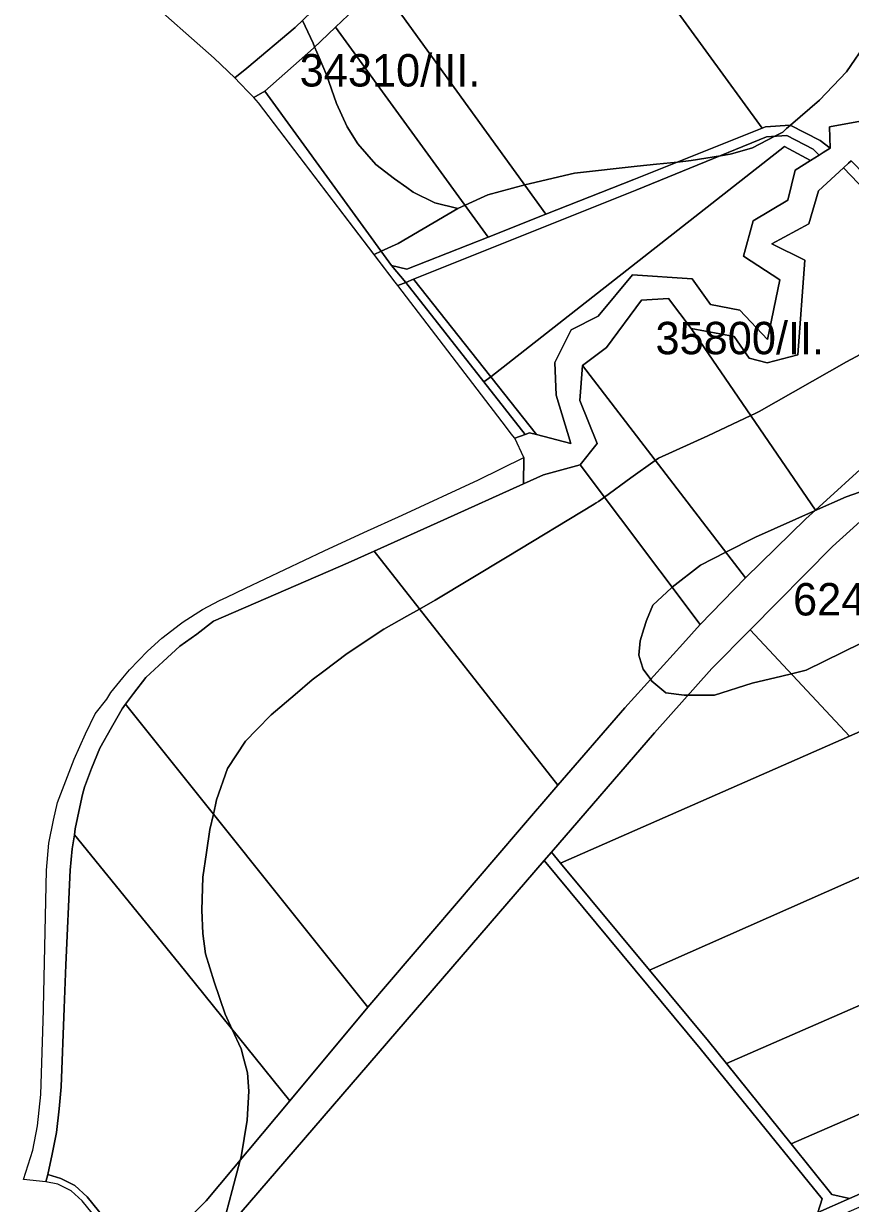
# Model space of a CAD drawing. Extents: x -522079 to -518792, y -1142400 to -1139961.
# Drawn here: x -521980 to -521597, y -1141010 to -1140463 of the extents above; entities that cross this region are included whole.
import ezdxf

# ---------------------------------------------------------------- set-up
doc = ezdxf.new("R2010")
doc.units = 0
for name, color, linetype in [('Hranice parcel', 7, 'Continuous'), ('Parcelní čísla', 7, 'Continuous'), ('Vnitřní kresba', 7, 'Continuous'), ('Značky bodu BP', 7, 'Continuous')]:
    doc.layers.add(name, color=color, linetype=linetype)

msp = doc.modelspace()

# ---------------------------------------------------------------- linework, layer by layer
at = {"layer": 'Hranice parcel'}
msp.add_lwpolyline([(-521829.77, -1140459.58), (-521835.62, -1140465.09), (-521845.84, -1140474.71), (-521868.24, -1140494.75), (-521873.47, -1140497.6), (-521875.9, -1140495.08), (-521879.74, -1140491.09), (-521882.18, -1140488.56), (-521876.66, -1140484.09), (-521854.3, -1140465.27), (-521839, -1140450.48)], dxfattribs=at)
at = {"layer": 'Parcelní čísla'}
for points in [[(-521592.51, -1140508.64), (-521606.9, -1140511.13), (-521606.6, -1140521.1), (-521611.18, -1140517.57), (-521625.07, -1140510.37), (-521636.41, -1140511.21), (-521638.02, -1140511.86), (-521742.3, -1140368.5), (-521728.93, -1140357.06), (-521708.67, -1140341.98), (-521697.12, -1140332.11), (-521688.85, -1140323.27), (-521680.22, -1140314.66), (-521674.58, -1140306.67), (-521664.44, -1140291.34), (-521641.46, -1140251.62), (-521633.25, -1140239.25), (-521625.36, -1140230.13), (-521613.09, -1140218.9), (-521610.22, -1140216.5), (-521608.33, -1140219.87), (-521596.95, -1140234.61)], [(-521925.13, -1141037.95), (-521895.5, -1141008.4), (-521856.78, -1140962.03), (-521820.63, -1140918.73), (-521750.36, -1140836.58), (-521732.61, -1140815.99), (-521701.61, -1140780.11), (-521674.73, -1140750.53), (-521666.78, -1140741.6), (-521645.77, -1140720.02), (-521617.82, -1140692.69), (-521613.36, -1140688.64), (-521587.52, -1140665.2)], [(-521576.52, -1140679.31), (-521605.53, -1140705.44), (-521643.56, -1140744), (-521661.3, -1140761.99), (-521687.87, -1140791.7), (-521735.53, -1140846.95), (-521738.91, -1140850.87), (-521884.07, -1141019.15)]]:
    msp.add_lwpolyline(points, dxfattribs=at)
for points in [[(-521924.65, -1140450.32), (-521818.63, -1140351.09), (-521781.95, -1140390.97), (-521803.88, -1140414.74), (-521822.79, -1140434.86), (-521839, -1140450.48), (-521854.3, -1140465.27), (-521876.66, -1140484.09), (-521882.18, -1140488.56), (-521891.73, -1140479.43)], [(-521747.91, -1140373.33), (-521742.3, -1140368.5), (-521638.02, -1140511.86), (-521697.45, -1140535.57), (-521738.18, -1140551.68), (-521815.4, -1140444.86), (-521814.39, -1140443.83), (-521794.87, -1140423.48), (-521773.82, -1140399.6), (-521757.78, -1140381.98)], [(-521829.77, -1140459.58), (-521815.4, -1140444.86), (-521738.18, -1140551.68), (-521764.87, -1140562.24), (-521835.62, -1140465.09)], [(-521835.62, -1140465.09), (-521764.87, -1140562.24), (-521802.53, -1140577.14), (-521809.71, -1140575.34), (-521868.24, -1140494.75), (-521845.84, -1140474.71)], [(-521809.71, -1140575.34), (-521803.08, -1140583.22), (-521806.71, -1140584.66), (-521807.95, -1140583.04), (-521871.3, -1140500.06), (-521873.47, -1140497.6), (-521868.24, -1140494.75)], [(-521802.53, -1140577.14), (-521764.87, -1140562.24), (-521738.18, -1140551.68), (-521697.45, -1140535.57), (-521638.02, -1140511.86), (-521636.41, -1140511.21), (-521625.07, -1140510.37), (-521611.18, -1140517.57), (-521606.6, -1140521.1), (-521609.78, -1140523.1), (-521611.69, -1140524.3), (-521614.4, -1140521.49), (-521626.56, -1140515.18), (-521635.99, -1140515.78), (-521696.07, -1140540.42), (-521799.46, -1140581.76), (-521803.08, -1140583.22), (-521809.71, -1140575.34)], [(-521614.4, -1140521.49), (-521611.69, -1140524.3), (-521615.57, -1140526.74), (-521627.73, -1140520.35), (-521763.73, -1140626.86), (-521799.46, -1140581.76), (-521696.07, -1140540.42), (-521635.99, -1140515.78), (-521626.56, -1140515.18)], [(-521646.65, -1140571), (-521629.87, -1140582.04), (-521635.54, -1140609.6), (-521648.43, -1140596.09), (-521661.89, -1140593.5), (-521670.5, -1140581.53), (-521698, -1140579.74), (-521713.89, -1140598.84), (-521726.52, -1140605.2), (-521734.01, -1140620.28), (-521733.38, -1140635.33), (-521726.67, -1140657.74), (-521742.5, -1140653.65), (-521763.73, -1140626.86), (-521627.73, -1140520.35), (-521615.57, -1140526.74), (-521622.75, -1140531.26), (-521626.2, -1140545.21), (-521642.26, -1140554.66)], [(-521521.75, -1140612.22), (-521600.31, -1140530.11), (-521598.04, -1140528.01), (-521596.8, -1140526.87), (-521570.34, -1140553.98), (-521517.85, -1140609.14)], [(-521587.52, -1140665.2), (-521613.36, -1140688.64), (-521670.89, -1140604.59), (-521650.96, -1140608.19), (-521643.99, -1140618.34), (-521635.78, -1140620.38), (-521621.47, -1140616.67), (-521618.3, -1140572.85), (-521633.5, -1140565.29), (-521616.47, -1140556.14), (-521611.96, -1140540.86), (-521600.31, -1140530.11), (-521521.75, -1140612.22), (-521556.8, -1140639.91)], [(-521799.46, -1140581.76), (-521763.73, -1140626.86), (-521766.84, -1140629.25), (-521803.08, -1140583.22)], [(-521806.71, -1140584.66), (-521803.08, -1140583.22), (-521766.84, -1140629.25), (-521747.72, -1140653.54), (-521752.49, -1140655.36), (-521754.23, -1140653.26), (-521756.45, -1140650.36)], [(-521613.36, -1140688.64), (-521617.82, -1140692.69), (-521645.77, -1140720.02), (-521721.28, -1140621.72), (-521710.1, -1140613.29), (-521693.94, -1140591.41), (-521681.44, -1140590.68), (-521670.89, -1140604.59)], [(-521714.47, -1140657.84), (-521722.39, -1140637.91), (-521721.28, -1140621.72), (-521645.77, -1140720.02), (-521666.78, -1140741.6), (-521722.24, -1140667.6)], [(-521424.45, -1140717.21), (-521517.19, -1140758), (-521597.52, -1140793.25), (-521643.56, -1140744), (-521605.53, -1140705.44), (-521576.52, -1140679.31), (-521545.43, -1140654.05), (-521509.24, -1140625.15)], [(-521763.73, -1140626.86), (-521742.5, -1140653.65), (-521745.77, -1140652.8), (-521747.72, -1140653.54), (-521766.84, -1140629.25)], [(-521674.73, -1140750.53), (-521701.61, -1140780.11), (-521732.61, -1140815.99), (-521817.76, -1140707.64), (-521785.36, -1140693.05), (-521748.53, -1140676.5), (-521739.27, -1140672.34), (-521722.24, -1140667.6), (-521666.78, -1140741.6)], [(-521820.63, -1140918.73), (-521932.78, -1140778.46), (-521929.14, -1140773.45), (-521923.36, -1140766.09), (-521915.35, -1140758.73), (-521907.65, -1140751.59), (-521899.73, -1140746), (-521892.09, -1140739.95), (-521829.78, -1140713), (-521817.76, -1140707.64), (-521732.61, -1140815.99), (-521750.36, -1140836.58)], [(-521589.34, -1140856.91), (-521690.16, -1140901.59), (-521731.35, -1140851.98), (-521597.52, -1140793.25), (-521517.19, -1140758), (-521424.45, -1140717.21), (-521383.31, -1140761.88), (-521381.12, -1140763.92), (-521473.38, -1140805.12)], [(-521735.53, -1140846.95), (-521687.87, -1140791.7), (-521661.3, -1140761.99), (-521643.56, -1140744), (-521597.52, -1140793.25), (-521731.35, -1140851.98)], [(-521589.34, -1140856.91), (-521473.38, -1140805.12), (-521381.12, -1140763.92), (-521343.03, -1140805.79), (-521433.97, -1140848.31), (-521555.85, -1140901.74), (-521654.5, -1140944.84), (-521662.84, -1140934.49), (-521690.16, -1140901.59)], [(-521856.78, -1140962.03), (-521908.14, -1140898.33), (-521956.51, -1140838.94), (-521956.06, -1140836.18), (-521953.99, -1140825.94), (-521952.78, -1140820.25), (-521951.85, -1140816.81), (-521948.6, -1140808.27), (-521944.68, -1140798.86), (-521939.28, -1140789.17), (-521934.35, -1140780.63), (-521932.78, -1140778.46), (-521820.63, -1140918.73)], [(-521343.03, -1140805.79), (-521311.05, -1140836.96), (-521307.59, -1140840.17), (-521401.58, -1140884.75), (-521526.28, -1140939.14), (-521624.6, -1140981.98), (-521654.5, -1140944.84), (-521555.85, -1140901.74), (-521433.97, -1140848.31)], [(-521968.74, -1140996.16), (-521966.75, -1140986.81), (-521964.79, -1140976.78), (-521963.61, -1140965.78), (-521962.64, -1140955.52), (-521961.27, -1140919.13), (-521960.41, -1140899.15), (-521958.48, -1140855.25), (-521957.55, -1140845.37), (-521956.51, -1140838.94), (-521908.14, -1140898.33), (-521856.78, -1140962.03), (-521895.5, -1141008.4), (-521925.13, -1141037.95), (-521927.04, -1141035.61), (-521950.59, -1141006.47), (-521956.25, -1141001.25), (-521962.85, -1140997.93)], [(-521526.28, -1140939.14), (-521401.58, -1140884.75), (-521307.59, -1140840.17), (-521288.46, -1140863.02), (-521289.17, -1140869.28), (-521455.15, -1140944.86), (-521597.65, -1141007.23), (-521605.69, -1141005.48), (-521624.6, -1140981.98)], [(-521690.16, -1140901.59), (-521662.84, -1140934.49), (-521654.5, -1140944.84), (-521624.6, -1140981.98), (-521605.69, -1141005.48), (-521597.65, -1141007.23), (-521612.22, -1141013.76), (-521610.31, -1141007.37), (-521666.76, -1140937.87), (-521738.91, -1140850.87), (-521735.53, -1140846.95), (-521731.35, -1140851.98)], [(-521666.76, -1140937.87), (-521610.31, -1141007.37), (-521612.22, -1141013.76), (-521737.51, -1141069.87), (-521813.35, -1141102.46), (-521884.07, -1141019.15), (-521738.91, -1140850.87)], [(-521288.46, -1140863.02), (-521283.24, -1140866.3), (-521272.67, -1140872.95), (-521285.04, -1140873.12), (-521453.3, -1140949.4), (-521594.31, -1141011.83), (-521607.81, -1141017.81), (-521735.67, -1141074.42), (-521844.44, -1141121.41), (-521845.59, -1141127.96), (-521855.85, -1141115.33), (-521847.83, -1141117.27), (-521813.35, -1141102.46), (-521737.51, -1141069.87), (-521612.22, -1141013.76), (-521597.65, -1141007.23), (-521455.15, -1140944.86), (-521289.17, -1140869.28)]]:
    msp.add_lwpolyline(points, close=True, dxfattribs=at)
at = {"layer": 'Vnitřní kresba'}
for points in [[(-521596.8, -1140526.87), (-521598.04, -1140528.01), (-521600.31, -1140530.11), (-521611.96, -1140540.86), (-521616.47, -1140556.14), (-521633.5, -1140565.29), (-521618.3, -1140572.85), (-521621.47, -1140616.67), (-521635.78, -1140620.38), (-521643.99, -1140618.34), (-521650.96, -1140608.19), (-521670.89, -1140604.59), (-521681.44, -1140590.68), (-521693.94, -1140591.41), (-521710.1, -1140613.29), (-521721.28, -1140621.72), (-521722.39, -1140637.91), (-521714.47, -1140657.84), (-521722.24, -1140667.6), (-521739.27, -1140672.34), (-521748.53, -1140676.5), (-521748.38, -1140664.24), (-521752.49, -1140655.36), (-521747.72, -1140653.54), (-521745.77, -1140652.8), (-521742.5, -1140653.65), (-521726.67, -1140657.74), (-521733.38, -1140635.33), (-521734.01, -1140620.28), (-521726.52, -1140605.2), (-521713.89, -1140598.84), (-521698, -1140579.74), (-521670.5, -1140581.53), (-521661.89, -1140593.5), (-521648.43, -1140596.09), (-521635.54, -1140609.6), (-521629.87, -1140582.04), (-521646.65, -1140571), (-521642.26, -1140554.66), (-521626.2, -1140545.21), (-521622.75, -1140531.26), (-521615.57, -1140526.74), (-521611.69, -1140524.3), (-521609.78, -1140523.1), (-521606.6, -1140521.1), (-521606.9, -1140511.13), (-521592.51, -1140508.64)], [(-521929.14, -1141037.67), (-521952.92, -1141008.37), (-521958.05, -1141003.66), (-521964.16, -1141000.63), (-521969.71, -1140999.55), (-521968.74, -1140996.16), (-521962.85, -1140997.93), (-521956.25, -1141001.25), (-521950.59, -1141006.47), (-521927.04, -1141035.61)]]:
    msp.add_lwpolyline(points, dxfattribs=at)
msp.add_lwpolyline([(-521968.74, -1140996.16), (-521969.71, -1140999.55), (-521980.02, -1140998.54), (-521975.77, -1140984.83), (-521973.56, -1140973.69), (-521972.01, -1140959.19), (-521970.73, -1140920.13), (-521970.78, -1140919.37), (-521969.35, -1140855.23), (-521968.4, -1140842.82), (-521966.23, -1140832.06), (-521964.35, -1140823.92), (-521960.5, -1140813.97), (-521956.64, -1140803.89), (-521951.34, -1140792.2), (-521946.81, -1140782.96), (-521941.53, -1140776.07), (-521939.58, -1140773.02), (-521933.99, -1140766.2), (-521930.99, -1140762.54), (-521922.69, -1140753.87), (-521915.99, -1140747.92), (-521907.36, -1140741.3), (-521906.16, -1140740.38), (-521897.11, -1140734.61), (-521889.34, -1140730.49), (-521885.86, -1140728.85), (-521877.29, -1140724.81), (-521840.82, -1140707.39), (-521822.52, -1140699.01), (-521804.78, -1140690.88), (-521769.34, -1140674.65), (-521748.38, -1140664.24), (-521748.53, -1140676.5), (-521785.36, -1140693.05), (-521817.76, -1140707.64), (-521829.78, -1140713), (-521892.09, -1140739.95), (-521899.73, -1140746), (-521907.65, -1140751.59), (-521915.35, -1140758.73), (-521923.36, -1140766.09), (-521929.14, -1140773.45), (-521932.78, -1140778.46), (-521934.35, -1140780.63), (-521939.28, -1140789.17), (-521944.68, -1140798.86), (-521948.6, -1140808.27), (-521951.85, -1140816.81), (-521952.78, -1140820.25), (-521953.99, -1140825.94), (-521956.06, -1140836.18), (-521956.51, -1140838.94), (-521957.55, -1140845.37), (-521958.48, -1140855.25), (-521960.41, -1140899.15), (-521961.27, -1140919.13), (-521962.64, -1140955.52), (-521963.61, -1140965.78), (-521964.79, -1140976.78), (-521966.75, -1140986.81)], close=True, dxfattribs=at)
at = {"layer": 'Značky bodu BP'}
for points in [[(-521850.83, -1140461.92), (-521845.96, -1140472.52), (-521845.26, -1140474.16), (-521843.12, -1140479.15), (-521839.74, -1140487.06), (-521835.19, -1140500.35), (-521830.22, -1140511.15), (-521825.25, -1140519.04), (-521816.97, -1140528.6), (-521808.28, -1140535.24), (-521802.62, -1140539.29), (-521799.58, -1140541.47), (-521789.65, -1140546.45), (-521778.88, -1140548.95), (-521806.62, -1140565.15), (-521814.45, -1140568.81), (-521817.66, -1140570.32), (-521871.3, -1140500.06), (-521873.47, -1140497.6), (-521875.9, -1140495.08), (-521879.74, -1140491.09), (-521882.18, -1140488.56), (-521891.73, -1140479.43), (-521924.65, -1140450.32)], [(-521589.25, -1140471.59), (-521598.91, -1140485.69), (-521611.51, -1140498.91), (-521624.87, -1140510.47), (-521626.68, -1140512.03), (-521628.5, -1140513.6), (-521630.26, -1140514.52), (-521632.2, -1140515.54), (-521642.55, -1140520.95), (-521651.63, -1140523.59), (-521652.89, -1140523.8), (-521657.38, -1140524.55), (-521670.97, -1140526.82), (-521677.18, -1140527.48), (-521687.01, -1140528.53), (-521695.86, -1140529.47), (-521724.86, -1140532.7), (-521745.36, -1140537.4), (-521747.99, -1140538.11), (-521764.98, -1140542.69), (-521775.62, -1140547.48), (-521778.88, -1140548.95), (-521789.65, -1140546.45), (-521799.58, -1140541.47), (-521802.62, -1140539.29), (-521808.28, -1140535.24), (-521816.97, -1140528.6), (-521825.25, -1140519.04), (-521830.22, -1140511.15), (-521835.19, -1140500.35), (-521839.74, -1140487.06), (-521843.12, -1140479.15), (-521845.26, -1140474.16), (-521845.96, -1140472.52), (-521850.83, -1140461.92)], [(-521929.14, -1141037.67), (-521952.92, -1141008.37), (-521958.05, -1141003.66), (-521964.16, -1141000.63), (-521969.71, -1140999.55), (-521980.02, -1140998.54), (-521975.77, -1140984.83), (-521973.56, -1140973.69), (-521972.01, -1140959.19), (-521970.73, -1140920.13), (-521970.78, -1140919.37), (-521969.35, -1140855.23), (-521968.4, -1140842.82), (-521966.23, -1140832.06), (-521964.35, -1140823.92), (-521960.5, -1140813.97), (-521956.64, -1140803.89), (-521951.34, -1140792.2), (-521946.81, -1140782.96), (-521941.53, -1140776.07), (-521939.58, -1140773.02), (-521933.99, -1140766.2), (-521930.99, -1140762.54), (-521922.69, -1140753.87), (-521915.99, -1140747.92), (-521907.36, -1140741.3), (-521906.16, -1140740.38), (-521897.11, -1140734.61), (-521889.34, -1140730.49), (-521885.86, -1140728.85), (-521877.29, -1140724.81), (-521840.82, -1140707.39), (-521822.52, -1140699.01), (-521804.78, -1140690.88), (-521769.34, -1140674.65), (-521748.38, -1140664.24), (-521752.49, -1140655.36), (-521754.23, -1140653.26), (-521756.45, -1140650.36), (-521806.71, -1140584.66), (-521807.95, -1140583.04), (-521817.66, -1140570.32), (-521814.45, -1140568.81), (-521806.62, -1140565.15), (-521778.88, -1140548.95), (-521775.62, -1140547.48), (-521764.98, -1140542.69), (-521747.99, -1140538.11), (-521745.36, -1140537.4), (-521724.86, -1140532.7), (-521695.86, -1140529.47), (-521687.01, -1140528.53), (-521677.18, -1140527.48), (-521670.97, -1140526.82), (-521657.38, -1140524.55), (-521652.89, -1140523.8), (-521651.63, -1140523.59), (-521642.55, -1140520.95), (-521632.2, -1140515.54), (-521630.26, -1140514.52), (-521628.5, -1140513.6), (-521626.68, -1140512.03), (-521624.87, -1140510.47), (-521611.51, -1140498.91), (-521598.91, -1140485.69), (-521589.25, -1140471.59)], [(-521575.67, -1140607.49), (-521598.95, -1140619.93), (-521639.43, -1140643.03), (-521641.26, -1140643.88), (-521643.33, -1140644.85), (-521663.22, -1140654.19), (-521685.99, -1140664.6), (-521687.51, -1140665.68), (-521698.9, -1140673.74), (-521711, -1140682.59), (-521713.82, -1140684.66), (-521714.9, -1140685.31), (-521715.85, -1140685.88), (-521756.08, -1140710.29), (-521789.48, -1140730.34), (-521796.7, -1140734.43), (-521802.6, -1140737.76), (-521813.26, -1140743.79), (-521830.22, -1140754.96), (-521841.02, -1140763.09), (-521846.41, -1140767.15), (-521854.34, -1140773.94), (-521865.39, -1140783.39), (-521872.05, -1140790.21), (-521877.28, -1140795.58), (-521885.63, -1140808.26), (-521890.69, -1140822.73), (-521890.84, -1140823.43), (-521891.19, -1140825.02), (-521892.14, -1140829.28), (-521893.73, -1140836.44), (-521895.32, -1140847.16), (-521897.01, -1140858.52), (-521897.52, -1140873.75), (-521897.01, -1140884.67), (-521895.75, -1140894.06), (-521891.7, -1140907), (-521886.64, -1140921.98), (-521883.43, -1140928.98), (-521879.3, -1140937.97), (-521877.98, -1140942.83), (-521876.27, -1140949.14), (-521875.76, -1140957.51), (-521876.52, -1140970.97), (-521879.3, -1140987.98), (-521879.69, -1140989.47), (-521883.38, -1141003.58), (-521886.14, -1141014.12)], [(-521886.14, -1141014.12), (-521883.38, -1141003.58), (-521879.69, -1140989.47), (-521879.3, -1140987.98), (-521876.52, -1140970.97), (-521875.76, -1140957.51), (-521876.27, -1140949.14), (-521877.98, -1140942.83), (-521879.3, -1140937.97), (-521883.43, -1140928.98), (-521886.64, -1140921.98), (-521891.7, -1140907), (-521895.75, -1140894.06), (-521897.01, -1140884.67), (-521897.52, -1140873.75), (-521897.01, -1140858.52), (-521895.32, -1140847.16), (-521893.73, -1140836.44), (-521892.14, -1140829.28), (-521891.19, -1140825.02), (-521890.84, -1140823.43), (-521890.69, -1140822.73), (-521885.63, -1140808.26), (-521877.28, -1140795.58), (-521872.05, -1140790.21), (-521865.39, -1140783.39), (-521854.34, -1140773.94), (-521846.41, -1140767.15), (-521841.02, -1140763.09), (-521830.22, -1140754.96), (-521813.26, -1140743.79), (-521802.6, -1140737.76), (-521796.7, -1140734.43), (-521789.48, -1140730.34), (-521756.08, -1140710.29), (-521715.85, -1140685.88), (-521714.9, -1140685.31), (-521713.82, -1140684.66), (-521711, -1140682.59), (-521698.9, -1140673.74), (-521687.51, -1140665.68), (-521685.99, -1140664.6), (-521663.22, -1140654.19), (-521643.33, -1140644.85), (-521641.26, -1140643.88), (-521639.43, -1140643.03), (-521598.95, -1140619.93), (-521575.67, -1140607.49)], [(-521592.12, -1140750.19), (-521617.61, -1140762.73), (-521624.5, -1140764.38), (-521628.89, -1140765.44), (-521642.6, -1140768.75), (-521660.09, -1140774.26), (-521672.27, -1140774.26), (-521674.08, -1140774.26), (-521682.58, -1140773.26), (-521689.08, -1140767.74), (-521689.65, -1140766.95), (-521693.08, -1140762.23), (-521694.13, -1140758.78), (-521695.07, -1140755.71), (-521694.57, -1140749.19), (-521692.81, -1140743.59), (-521691.58, -1140739.67), (-521688.58, -1140732.65), (-521680.08, -1140724.62), (-521679.71, -1140724.34), (-521666.59, -1140714.1), (-521654.91, -1140708.12), (-521641.1, -1140701.06), (-521613.72, -1140688.96), (-521599.12, -1140682.51), (-521566.13, -1140670.87)], [(-521566.13, -1140670.87), (-521599.12, -1140682.51), (-521613.72, -1140688.96), (-521641.1, -1140701.06), (-521654.91, -1140708.12), (-521666.59, -1140714.1), (-521679.71, -1140724.34), (-521680.08, -1140724.62), (-521688.58, -1140732.65), (-521691.58, -1140739.67), (-521692.81, -1140743.59), (-521694.57, -1140749.19), (-521695.07, -1140755.71), (-521694.13, -1140758.78), (-521693.08, -1140762.23), (-521689.65, -1140766.95), (-521689.08, -1140767.74), (-521682.58, -1140773.26), (-521674.08, -1140774.26), (-521672.27, -1140774.26), (-521660.09, -1140774.26), (-521642.6, -1140768.75), (-521628.89, -1140765.44), (-521624.5, -1140764.38), (-521617.61, -1140762.73), (-521592.12, -1140750.19)]]:
    msp.add_lwpolyline(points, dxfattribs=at)

# ---------------------------------------------------------------- texts
for s, p in [('34310/III.', (-521852.16, -1140492.53)), ('35800/II.', (-521687.42, -1140616.47)), ('62411/III.', (-521623.72, -1140737.38))]:
    msp.add_text(s, height=15, rotation=0, dxfattribs=at).set_placement(p)

doc.saveas('drawing.dxf')
